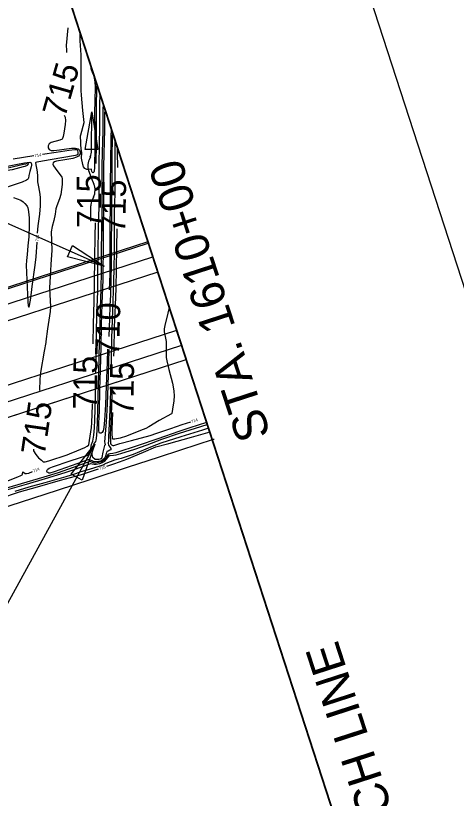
# Model space of a CAD drawing. Extents: x -468563856 to 36492962, y -306094093 to 11899197.
# Drawn here: x 1826935 to 1827540, y 532272 to 533347 of the extents above; entities that cross this region are included whole.
import ezdxf

# ---------------------------------------------------------------- set-up
doc = ezdxf.new("R2010")
doc.units = 0
for name, color, linetype in [('Default', 7, 'Continuous'), ('DT_X_Contour_Minor', 7, 'Continuous'), ('DT_X_Terrain_Ground_Line', 7, 'Continuous'), ('Level 14', 7, 'Continuous'), ('Level 19', 7, 'Continuous'), ('Level 31', 7, 'Continuous'), ('Level 40', 7, 'Continuous'), ('SC_Scratch1', 7, 'Continuous'), ('SC_Shading3', 7, 'Continuous'), ('SH_Border', 7, 'Continuous'), ('SH_Data', 7, 'Continuous')]:
    doc.layers.add(name, color=color, linetype=linetype)

msp = doc.modelspace()

# ---------------------------------------------------------------- linework, layer by layer
at = {"layer": 'Default'}
for points in [[(1824453.9, 532170), (1824460.1, 532150.9), (1827123.3, 533015.5), (1827116.5, 533036.4)], [(1824499.7, 532029.1), (1824505.9, 532010), (1827169, 532874.6), (1827162.8, 532893.7)]]:
    msp.add_lwpolyline(points, close=True, dxfattribs=at)
at = {"layer": 'DT_X_Contour_Minor'}
for points in [[(1827006.6, 533330.5), (1827004.4, 533306), (1827004.8, 533299.8), (1827004.9, 533296.7)], [(1827043, 533138.5), (1827042.8, 533133.6), (1827042.4, 533132.2), (1827041.7, 533131.4), (1827040.8, 533131.3), (1827040, 533131.9), (1827039.5, 533132.9), (1827039.1, 533135.9), (1827038.7, 533136), (1827035.3, 533135.6), (1827032.6, 533135.7), (1827030.1, 533136.9), (1827028.3, 533139.4), (1827027.1, 533142.8), (1827025.3, 533151.4), (1827025.2, 533153.4), (1827025.6, 533156.4), (1827026, 533158.7), (1827024.8, 533164.4), (1827024.6, 533169.6), (1827024.5, 533172.6), (1827024.1, 533182.2), (1827024.3, 533183.4), (1827029, 533200.4), (1827027.3, 533217), (1827025.2, 533238), (1827024.7, 533244.4), (1827024.8, 533255.1), (1827025.1, 533286.6), (1827024.7, 533293.1), (1827023.3, 533312.7), (1827023.3, 533317.6), (1827023.6, 533321.4), (1827023.7, 533322.2)], [(1827037.5, 533279.8), (1827038.3, 533274.4), (1827040, 533269.4), (1827041.7, 533265.3), (1827042.9, 533261.2), (1827043.7, 533256.3), (1827044, 533249.5), (1827043.7, 533230.3), (1827043.3, 533213.9), (1827043.5, 533190), (1827043.5, 533167.3), (1827043, 533138.5)], [(1827045.3, 533143.9), (1827045.8, 533171.3), (1827045.8, 533191.2), (1827045.8, 533220.4), (1827046.6, 533249.3), (1827046.7, 533251.5)], [(1827045.1, 532856.3), (1827045.6, 532879.9), (1827046.1, 532912.1), (1827046.6, 532935.7), (1827047.6, 532968.2), (1827048, 532992.7), (1827048.3, 533023), (1827048.8, 533055), (1827049.4, 533085.3), (1827049.5, 533110.3), (1827049.6, 533141.8), (1827050.1, 533169.9), (1827050.4, 533193.6), (1827050.6, 533225.3), (1827051, 533238.3)], [(1827062.7, 532888.3), (1827062.2, 532870.7), (1827061.3, 532838.6), (1827060.4, 532813.4), (1827059.1, 532788.3), (1827057.1, 532761.5), (1827057.5, 532759.5), (1827057.8, 532757.6), (1827057, 532756.6), (1827056.3, 532754.8), (1827054.8, 532747.3), (1827053.4, 532739.8), (1827052.6, 532738.8), (1827051.2, 532737.9), (1827049.2, 532737.1), (1827047, 532737.1), (1827044.3, 532737.3), (1827040.9, 532740.1), (1827040.4, 532741.8), (1827040, 532744.1), (1827040, 532746.3), (1827040.5, 532748.2), (1827040.4, 532751.8), (1827040.4, 532753.3), (1827041.8, 532757.1), (1827042.3, 532758.2), (1827045.1, 532762), (1827045.6, 532763.6), (1827046, 532766.1), (1827046.8, 532776.6), (1827047.9, 532800.9), (1827048.4, 532825), (1827049, 532853), (1827049.8, 532880.5), (1827050.5, 532910.3), (1827051.3, 532944.3), (1827052.2, 532972.1), (1827052.9, 532995.2), (1827053, 533022.3), (1827053.3, 533051.9), (1827053.5, 533080), (1827053.8, 533110.5), (1827053.9, 533140.2), (1827054.2, 533158.9), (1827054.9, 533189), (1827055.3, 533218.9), (1827055.4, 533224.5)], [(1827060.9, 532888.7), (1827060.4, 532870.7), (1827059.3, 532838.6), (1827058.2, 532812.3), (1827057.1, 532791.3), (1827056, 532781.2), (1827055, 532776.7), (1827053.8, 532774.2), (1827052.5, 532773.3), (1827050.2, 532773.5), (1827049.5, 532774.5), (1827049.1, 532777.1), (1827049.3, 532787.2), (1827049.9, 532803.7), (1827050.6, 532833.2), (1827051.3, 532859.9), (1827052.3, 532892), (1827052.9, 532921.7), (1827053.7, 532951), (1827055, 532984.6), (1827055.3, 532996.4), (1827055.4, 533025.6), (1827055.6, 533054), (1827055.8, 533085.5), (1827055.9, 533106.6), (1827056.1, 533139.5), (1827056.4, 533157.2), (1827057.2, 533190.6), (1827057.6, 533215.1)], [(1827001.5, 533210.5), (1827002.8, 533207.6), (1827003.3, 533202.9), (1827003, 533197.6), (1827001.2, 533185.7), (1827000.3, 533181), (1826999.4, 533178.4), (1826998.6, 533177.2), (1826995.8, 533176.2), (1826983.7, 533172.9), (1826980.9, 533171), (1826979.4, 533168.3), (1826979.4, 533165.3), (1826980.9, 533163.1), (1826983.8, 533162), (1826987.3, 533161.9), (1826995.2, 533162.9), (1827004.8, 533164.3), (1827011.5, 533165), (1827017.3, 533165.1), (1827020.8, 533164), (1827022.5, 533162.4), (1827023.4, 533159.5), (1827023.3, 533157.3), (1827022.7, 533155.8), (1827021.3, 533154.1), (1827018.3, 533152.5), (1827013.3, 533151), (1827002.3, 533148.9), (1826990.9, 533147), (1826988.2, 533146.2), (1826986.5, 533145), (1826986.1, 533143.2), (1826987.1, 533140.7), (1826989.1, 533137.6), (1826998.2, 533125.1), (1826998.7, 533123.2), (1826998.8, 533120.1), (1826998.6, 533114.9), (1826998.1, 533108.3), (1826997, 533101.5), (1826995.2, 533095.5), (1826991.3, 533085.9), (1826990.3, 533081.9), (1826989.3, 533074.3), (1826987.2, 533065.6), (1826985.2, 533057.3), (1826983.8, 533050), (1826984.7, 533025.1), (1826983.4, 533005.3), (1826982.5, 532988.6), (1826981.6, 532973.2), (1826981.9, 532963.5), (1826982.8, 532947.4), (1826982.1, 532940.8), (1826978.5, 532917), (1826976.4, 532899.5), (1826976.2, 532897.8), (1826973.9, 532886.1), (1826968.9, 532856.7), (1826968, 532847.5), (1826967.5, 532831.9)], [(1827066, 533192), (1827065.7, 533180.4), (1827065, 533145.5), (1827064.8, 533116.3), (1827064.6, 533087.4), (1827064.4, 533055.5), (1827064.3, 533026.6), (1827064.1, 532992), (1827063.3, 532970.6)], [(1827067.7, 533186.8), (1827067.6, 533180.8), (1827067, 533152.3), (1827067, 533128.7), (1827066.7, 533093.8), (1827066.4, 533066.3), (1827066.2, 533035.4), (1827066.1, 533004.9), (1827065.7, 532984), (1827065, 532963.7), (1827064.4, 532948.4), (1827063.7, 532931.1), (1827063.1, 532906.2)], [(1827071.1, 533176.1), (1827071.1, 533173.2), (1827071, 533155.6), (1827071.2, 533129.2), (1827070.9, 533103), (1827070.4, 533075.6), (1827070.2, 533050.2), (1827070, 533023.4), (1827069.8, 532998.7), (1827068.9, 532966.5), (1827068.6, 532957.6), (1827067.3, 532928.7), (1827066.6, 532903.8), (1827066, 532870.8), (1827065.6, 532854.4)], [(1826965.1, 533048.1), (1826965.6, 533058.2), (1826968.2, 533074.5), (1826969, 533085.9), (1826969.1, 533091.5), (1826969, 533096.8), (1826968.5, 533102), (1826966.7, 533111.9), (1826965.5, 533118.7), (1826965.4, 533122.5), (1826965.4, 533126.4), (1826964.8, 533132.7), (1826962.7, 533144.7), (1826962.5, 533145.3), (1826962.9, 533145.8), (1826964.5, 533146.3), (1826972, 533147.8), (1826998.3, 533152.1), (1827017.1, 533155.4), (1827019.1, 533155.9), (1827020.2, 533156.6), (1827020.8, 533157.3), (1827020.9, 533159.1), (1827020.3, 533161.8), (1827019.7, 533162.5), (1827018.4, 533162.9), (1827016.1, 533162.9), (1827008.3, 533161.8), (1826990.6, 533159), (1826972, 533156.4)], [(1827075.2, 533138.3), (1827075, 533158.9), (1827075, 533164.3)], [(1826960.1, 533154.7), (1826931.6, 533149.8)], [(1826945.2, 533139.2), (1826929.9, 533135.5), (1826921.1, 533133.8), (1826900.3, 533130.5), (1826879.4, 533127.4), (1826869.9, 533125.5), (1826865.9, 533125.2), (1826860.8, 533125.1), (1826856.1, 533125.4), (1826854.1, 533126), (1826856, 533127), (1826865.4, 533129.1), (1826873, 533130.4), (1826901.3, 533134.6), (1826922.3, 533137.8), (1826945.8, 533142.9), (1826952.3, 533144.1), (1826952.4, 533143.6), (1826952.1, 533142.7), (1826951.6, 533142), (1826950.7, 533141.2), (1826947.6, 533140), (1826945.2, 533139.2)], [(1826911.4, 533138.2), (1826935.3, 533142.7), (1826946.9, 533144.8), (1826954.5, 533145.6), (1826955.8, 533145.2), (1826956.4, 533144.4), (1826956.7, 533143.2), (1826956.8, 533141.5), (1826956.4, 533139.2), (1826954.6, 533133), (1826953.1, 533127.4), (1826952.5, 533124), (1826952.1, 533122.9), (1826951.2, 533121.9), (1826949.6, 533120.9), (1826943.9, 533118.4), (1826937.2, 533116), (1826912.1, 533108)], [(1826932.1, 533097.1), (1826937.1, 533095.6), (1826941.8, 533093.6), (1826945.3, 533091.5), (1826947.7, 533089.2), (1826950.6, 533085.2), (1826951.5, 533083.2), (1826952.1, 533080.8), (1826952.7, 533077.7), (1826953.4, 533069.4), (1826953.4, 533059.1), (1826952.8, 533043.1), (1826951.8, 533030.8), (1826950.6, 533019.1), (1826949.6, 533010.6), (1826949.5, 533004.2), (1826950.2, 532983.9), (1826951.7, 532953.9), (1826952.3, 532948.7), (1826953.1, 532946.4), (1826954.1, 532948.7), (1826955.8, 532959.1), (1826957.6, 532975), (1826961.9, 533004.2), (1826963.1, 533015.9), (1826964.4, 533036.1)], [(1827041.5, 532896.3), (1827041.9, 532923.7), (1827042.7, 532954.3), (1827043.1, 532979.3), (1827043.5, 533014.2), (1827044.2, 533043.5), (1827044.7, 533062.5)], [(1827069.9, 532879.3), (1827070, 532887.1), (1827070.5, 532919.2), (1827072, 532949.1), (1827073, 532972.4), (1827073.6, 532999.7), (1827073.9, 533028.3), (1827074.1, 533054.1)], [(1827145.8, 532946.1), (1827144.1, 532938.4), (1827139.9, 532921.3), (1827139.1, 532916.8), (1827139, 532912.6), (1827139.7, 532908.4), (1827141.5, 532899.4), (1827141.8, 532894.5), (1827141.4, 532881.2), (1827141.7, 532877.3), (1827142.5, 532872.7), (1827145.4, 532860.7), (1827150.3, 532842.1), (1827151.2, 532837.2), (1827152, 532831.2), (1827152.4, 532824.6), (1827152, 532817.8), (1827150.5, 532806.5), (1827149.5, 532800.4), (1827149, 532800), (1827132, 532790.7), (1827117.6, 532781.9), (1827113.8, 532780), (1827106.6, 532777.2), (1827087.1, 532769.3), (1827078.5, 532766.6), (1827071.2, 532765.2), (1827068.7, 532765.1), (1827068.1, 532765.6), (1827067.4, 532773.4), (1827067.5, 532778.4), (1827068.4, 532801.9)], [(1827065.2, 532834.8), (1827064.7, 532815.7), (1827063.4, 532786.2), (1827062.4, 532768.2), (1827062.3, 532762.9), (1827062.1, 532759.5), (1827062.5, 532757.1), (1827063.8, 532755.1), (1827065.7, 532752.3), (1827065.8, 532751.5), (1827065.4, 532750.7), (1827064.3, 532749.9), (1827061.8, 532748.7), (1827060.1, 532748), (1827059.6, 532746.2), (1827058.5, 532742), (1827057.2, 532739.4), (1827055.6, 532737.5), (1827053.3, 532735.9), (1827051.5, 532735), (1827048.9, 532734.3), (1827043.7, 532733.9), (1827041.9, 532734.4), (1827036, 532737.2), (1827034.2, 532736.7), (1827019.1, 532731.3), (1826987.9, 532720.1), (1826981.9, 532718.4), (1826980.4, 532718.4), (1826979.1, 532719.2), (1826978.4, 532719.8), (1826977.9, 532720.6), (1826977.8, 532721.5), (1826978.6, 532723.6), (1826978.9, 532724.1), (1826981.1, 532725.3), (1826985.7, 532727.2), (1827009.9, 532735.2), (1827033.9, 532743.1), (1827034.7, 532743.9), (1827036.5, 532746.6), (1827037.6, 532749.1), (1827039.2, 532758.4), (1827040.1, 532760.3), (1827040.7, 532762.6), (1827042.1, 532770.8), (1827043.1, 532780.6), (1827043.7, 532791.7), (1827044.5, 532820.7), (1827044.7, 532834.6)], [(1827067.2, 532832.7), (1827067.2, 532830), (1827066.5, 532810.1), (1827065.2, 532779.2), (1827064.9, 532772.2), (1827065.1, 532759.8), (1827065.8, 532758.4), (1827066.7, 532757.3), (1827068.4, 532756.3), (1827069.8, 532756.4), (1827072.6, 532757.2), (1827078.1, 532759.1), (1827094.1, 532763.5), (1827119.5, 532770.1), (1827128.9, 532773.2), (1827148, 532779.8), (1827163.6, 532785.2), (1827175.3, 532789)], [(1826959.5, 532751.3), (1826959.6, 532749), (1826962.4, 532744.3), (1826966.5, 532739.7), (1826970.3, 532736.1), (1826972.9, 532734.2), (1826975.5, 532734), (1826980.3, 532735.3), (1827005.7, 532743.8), (1827012, 532746.2), (1827013.3, 532747), (1827029.7, 532753.7), (1827033.1, 532755.4), (1827034.9, 532756.7), (1827035.5, 532757.6), (1827038.9, 532781.1), (1827039.6, 532787.6), (1827040.3, 532811.8), (1827040.4, 532813.8)], [(1827197.1, 532788.1), (1827174.1, 532780.6), (1827159.1, 532775.6), (1827130.3, 532765.7), (1827103.3, 532756.6), (1827072.7, 532746.5), (1827068.5, 532745.5), (1827064.3, 532745.1), (1827062.7, 532744.5), (1827061.5, 532743.5), (1827058.2, 532738), (1827056, 532735.9), (1827052.9, 532734.1), (1827049.1, 532732.9), (1827044.5, 532732.3), (1827041.8, 532732.5), (1827039.3, 532733.6), (1827037.2, 532734.6), (1827036.7, 532734.6), (1827031.7, 532732.8), (1827013.9, 532726.2), (1826993.3, 532719), (1826973.8, 532713.1), (1826942.7, 532704), (1826912.5, 532695.3)], [(1826920.8, 532695), (1826949.7, 532703.3), (1826975.9, 532711), (1827003.1, 532719.2), (1827016.5, 532723.8), (1827038, 532731.8), (1827039.8, 532731.3), (1827042.6, 532730.7), (1827045.7, 532730.8), (1827050.4, 532731.8), (1827054.2, 532733.2), (1827057.2, 532735.1), (1827059.9, 532737.7), (1827062.1, 532740.5), (1827063.6, 532742.5), (1827064.9, 532742.8), (1827069.3, 532743.1), (1827073, 532743.8), (1827079.3, 532745.4), (1827098.8, 532751.6), (1827115.4, 532757.5), (1827135.8, 532765), (1827160, 532773.3), (1827181.9, 532780.3), (1827198, 532785.4)], [(1827199.7, 532780.1), (1827191.6, 532777.6), (1827161.9, 532768.3), (1827134.4, 532759.5), (1827122.2, 532754.9), (1827096.3, 532744.2), (1827085.3, 532740.2), (1827079.7, 532738.7), (1827075.6, 532737.9), (1827070.7, 532736.3), (1827058.7, 532731.6), (1827054.7, 532729.5), (1827050.3, 532727.9), (1827035.7, 532723.3), (1827024.4, 532720.1), (1827017.2, 532717.6), (1827003.7, 532713.5), (1826975.2, 532705.3), (1826952.9, 532699), (1826933.7, 532693.4)], [(1827060.1, 532728), (1827069.6, 532731.1), (1827077.5, 532733.9), (1827087.4, 532737.6), (1827110.3, 532747.2), (1827127.6, 532754.4), (1827145.4, 532759.3), (1827176.5, 532768), (1827198.8, 532774.5), (1827201.3, 532775.2)], [(1826910.7, 532702.9), (1826937.9, 532713.4), (1826942, 532715.1), (1826943.8, 532716), (1826944.2, 532716.9), (1826944.6, 532720.2), (1826947.8, 532717.9), (1826949.8, 532717.8), (1826952.8, 532718.6), (1826958.1, 532720.8)], [(1826912.6, 532683.7), (1826940.4, 532692.8), (1826964.8, 532699.7), (1826996.4, 532708.6), (1827023.8, 532716.3), (1827048.7, 532724.3)]]:
    msp.add_lwpolyline(points, dxfattribs=at)
at = {"layer": 'DT_X_Terrain_Ground_Line'}
msp.add_line((1827446.9, 532018.9), (1826839.3, 533890.3), dxfattribs=at)
at = {"layer": 'Level 14'}
msp.add_lwpolyline([(1827207.7, 532764.9), (1827206.4, 532764.5), (1827161.5, 532749.9), (1827130.7, 532739.9), (1827089.6, 532726.5), (1827038.1, 532709.8), (1826991.7, 532694.8), (1826942.5, 532678.7), (1826893.9, 532662.9)], dxfattribs=at)
at = {"layer": 'Level 31'}
for p, q in [((1827030.6, 533163.2), (1827039.5, 533214.8)), ((1827039.2, 533161.8), (1827039.5, 533214.8)), ((1827039.5, 533214.8), (1827047.8, 533163.2)), ((1827047.8, 533163.2), (1827030.6, 533163.2)), ((1827037.5, 533153.3), (1827035.7, 533149.2)), ((1827035.7, 533132.1), (1827039.2, 533123.5)), ((1827039.2, 533123.5), (1827042.3, 533115.8)), ((1827041.9, 533097.9), (1827040, 533093.6)), ((1827038.1, 533064.8), (1827038.2, 533085.7))]:
    msp.add_line(p, q, dxfattribs=at)
for centre, radius, start, end in [((1827016.8, 533161.9), 22.4, 337.3227, 359.6827), ((1827056.4, 533140.5), 22.4, 157.2839, 202.1277), ((1827021.6, 533107.3), 22.4, 335.15, 22.2585), ((1827057.4, 533085.6), 19.2, 155.1999, 179.6827)]:
    msp.add_arc(centre, radius, start, end, dxfattribs=at)
at = {"layer": 'Level 40'}
for p, q in [((1826590.7, 533209.3), (1827056.6, 533002.7)), ((1827005.9, 533015.7), (1827012.9, 533031.4)), ((1827012.9, 533031.4), (1827056.6, 533002.7)), ((1827056.6, 533002.7), (1827005.9, 533015.7)), ((1827011.3, 532717.2), (1827043.6, 532758.3)), ((1827043.6, 532758.3), (1827026.3, 532708.9)), ((1827026.3, 532708.9), (1827011.3, 532717.2))]:
    msp.add_line(p, q, dxfattribs=at)
msp.add_lwpolyline([(1827043.6, 532758.3), (1826923.9, 532539.4), (1826852.5, 532516.3)], dxfattribs=at)
at = {"layer": 'SC_Scratch1'}
msp.add_lwpolyline([(1818754.7, 531265.4), (1818680.3, 532626), (1826365, 535120.9), (1826839.3, 533890.3), (1827446.9, 532018.9), (1827532.1, 531348.3), (1819682.5, 528840.1), (1819362.2, 529394.3)], close=True, dxfattribs=at)
at = {"layer": 'SC_Shading3'}
for points in [[(1824466.9, 532129.9), (1824453.9, 532170), (1827117.1, 533034.5), (1827130.1, 532994.5)], [(1824492.9, 532050), (1824505.8, 532010.1), (1827169, 532874.7), (1827156, 532914.7)]]:
    msp.add_lwpolyline(points, close=True, dxfattribs=at)
at = {"layer": 'SH_Border'}
msp.add_line((1828514.3, 530006.7), (1826568.9, 535998.8), dxfattribs=at)

# ---------------------------------------------------------------- texts
at = {"layer": 'DT_X_Terrain_Ground_Line'}
msp.add_text('MATCH LINE                 STA. 1610+00', height=46.8, rotation=107.9864, dxfattribs=at).set_placement((1827493.8, 532129.6))
at = {"layer": 'Level 19'}
for s, height, rotation, p in [('715', 33, 74.0204, (1827002.7, 533205.7)), ('714', 4, 7.9813, (1826961.2, 533152.8)), ('715', 33, 90.0976, (1827052, 533055.4)), ('715', 33, 89.009, (1827085.5, 533048)), ('714', 4, 86.5739, (1826966.4, 533036.8)), ('710', 33, 88.3845, (1827076.8, 532879)), ('715', 33, 89.3871, (1827046.7, 532805.9)), ('715', 33, 89.347, (1827096.7, 532797.5)), ('715', 33, 81.6751, (1826974.7, 532741.8)), ('714', 4, 17.9794, (1827176.7, 532787.3)), ('718', 4, 17.9851, (1827050.1, 532722.6)), ('714', 4, 22.4599, (1826959.6, 532719.2))]:
    msp.add_text(s, height=height, rotation=rotation, dxfattribs=at).set_placement(p)
at = {"layer": 'SH_Data'}
msp.add_text('PROJECT SITE PLAN', height=75, rotation=107.9864, dxfattribs=at).set_placement((1827862.9, 532863.1))

doc.saveas('drawing.dxf')
